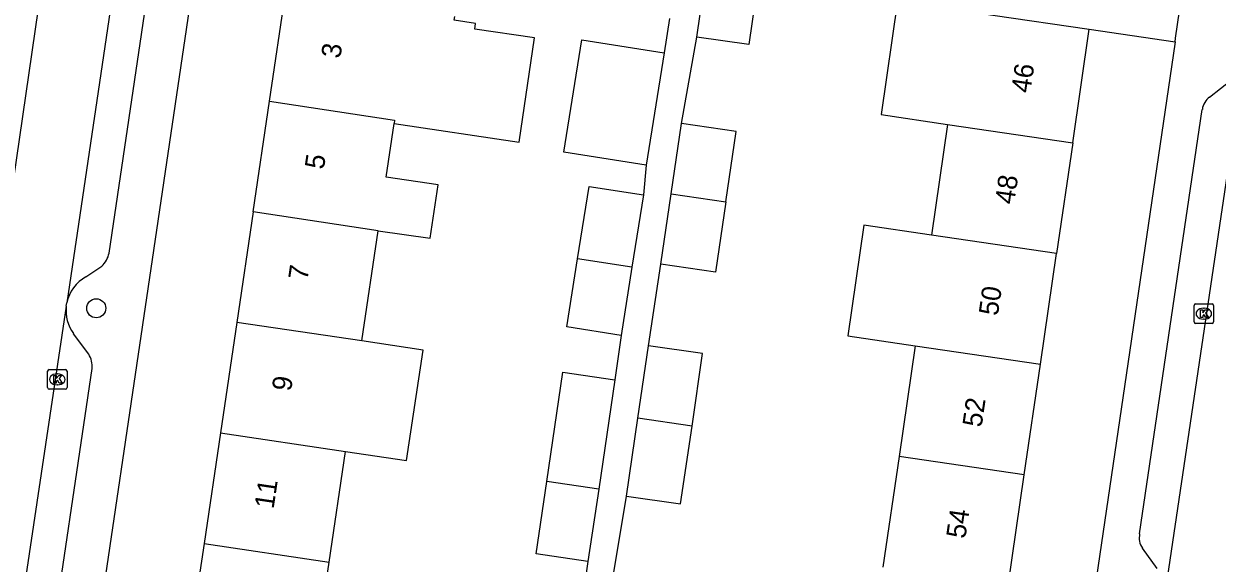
# Model space of a CAD drawing. Extents: x 163686 to 164493, y 382719 to 383870.
# Drawn here: x 163796.1 to 163857.4, y 383079.3 to 383107 of the extents above; entities that cross this region are included whole.
import ezdxf

# ---------------------------------------------------------------- set-up
doc = ezdxf.new("R2010")
doc.units = 0
for name, color, linetype in [('IMGEO_Boom', 7, 'Continuous'), ('IMGEO_Kolk', 7, 'Continuous'), ('IMGEO_Pand', 7, 'Continuous'), ('IMGEO_Pand_nummerreeks', 7, 'Continuous'), ('IMGEO_Rijbaan_lokaal_open', 7, 'Continuous'), ('IMGEO_Voetpad_open', 7, 'Continuous')]:
    doc.layers.add(name, color=color, linetype=linetype)

msp = doc.modelspace()

# ---------------------------------------------------------------- linework, layer by layer
at = {"layer": 'IMGEO_Boom'}
msp.add_circle((163799.849, 383092.402), 0.489, dxfattribs=at)
at = {"layer": 'IMGEO_Kolk'}
for p, q in [((163856.263, 383091.699), (163856.263, 383092.551)), ((163856.338, 383092.625), (163857.19, 383092.625)), ((163856.751, 383092.405), (163856.776, 383092.405)), ((163857.264, 383092.551), (163857.264, 383091.699)), ((163857.19, 383091.625), (163856.338, 383091.625)), ((163856.774, 383091.845), (163856.749, 383091.845)), ((163797.347, 383088.321), (163797.347, 383089.173)), ((163797.422, 383089.247), (163798.274, 383089.247)), ((163797.835, 383089.027), (163797.86, 383089.027)), ((163798.348, 383089.173), (163798.348, 383088.321)), ((163797.858, 383088.467), (163797.833, 383088.467)), ((163798.274, 383088.247), (163797.422, 383088.247))]:
    msp.add_line(p, q, dxfattribs=at)
for points in [[(163856.263, 383091.699), (163856.263, 383092.551)], [(163856.338, 383092.625), (163857.19, 383092.625)], [(163856.584, 383092.325), (163856.707, 383092.325), (163856.707, 383092.174), (163856.837, 383092.325), (163857.001, 383092.325), (163856.855, 383092.174), (163857.008, 383091.925), (163856.856, 383091.925), (163856.771, 383092.089), (163856.707, 383092.022), (163856.707, 383091.925), (163856.584, 383091.925), (163856.584, 383092.325)], [(163857.264, 383092.551), (163857.264, 383091.699)], [(163857.19, 383091.625), (163856.338, 383091.625)], [(163797.347, 383088.321), (163797.347, 383089.173)], [(163797.422, 383089.247), (163798.274, 383089.247)], [(163798.348, 383089.173), (163798.348, 383088.321)], [(163797.668, 383088.947), (163797.791, 383088.947), (163797.791, 383088.796), (163797.921, 383088.947), (163798.085, 383088.947), (163797.939, 383088.796), (163798.092, 383088.547), (163797.94, 383088.547), (163797.855, 383088.711), (163797.791, 383088.644), (163797.791, 383088.547), (163797.668, 383088.547), (163797.668, 383088.947)], [(163798.274, 383088.247), (163797.422, 383088.247)]]:
    msp.add_lwpolyline(points, dxfattribs=at)
for centre, start, end in [((163856.34, 383092.549), 91.55205, 178.44795), ((163856.34, 383092.549), 91.55205, 178.44795), ((163857.188, 383092.549), 1.55205, 88.44795), ((163857.188, 383092.549), 1.55205, 88.44795), ((163856.34, 383091.701), 181.55205, 268.44795), ((163856.34, 383091.701), 181.55205, 268.44795), ((163857.188, 383091.701), 271.55205, 358.44795), ((163857.188, 383091.701), 271.55205, 358.44795), ((163797.424, 383089.171), 91.55205, 178.44795), ((163797.424, 383089.171), 91.55205, 178.44795), ((163798.272, 383089.171), 1.55205, 88.44795), ((163798.272, 383089.171), 1.55205, 88.44795), ((163797.424, 383088.323), 181.55205, 268.44795), ((163797.424, 383088.323), 181.55205, 268.44795), ((163798.272, 383088.323), 271.55205, 358.44795), ((163798.272, 383088.323), 271.55205, 358.44795)]:
    msp.add_arc(centre, 0.0765, start, end, dxfattribs=at)
for centre, major_axis, ratio, start_param, end_param in [((163856.75, 383092.125), (-0.387, 0.002), 0.722429, 4.712389, 7.853982), ((163856.775, 383092.125), (-0.39, 0.002), 0.717154, 1.570796, 4.712389), ((163797.834, 383088.747), (-0.387, 0.002), 0.722429, 4.712389, 7.853982), ((163797.859, 383088.747), (-0.39, 0.002), 0.717154, 1.570796, 4.712389)]:
    msp.add_ellipse(centre, major_axis=major_axis, ratio=ratio, start_param=start_param, end_param=end_param, dxfattribs=at)
at = {"layer": 'IMGEO_Pand'}
for points in [[(163830.71, 383106.346), (163831.213, 383109.792), (163833.884, 383109.402)], [(163833.884, 383109.402), (163833.381, 383105.956), (163830.71, 383106.346)], [(163808.748, 383103.042), (163809.589, 383108.724)], [(163841.028, 383108.189), (163840.176, 383102.357), (163843.591, 383101.856)], [(163841.028, 383108.189), (163844.442, 383107.69), (163845.928, 383107.473), (163850.875, 383106.752)], [(163815.154, 383101.897), (163821.579, 383100.946), (163822.371, 383106.3), (163819.298, 383106.755), (163819.341, 383107.047), (163818.246, 383107.209), (163818.276, 383107.409)], [(163828.114, 383099.754), (163823.878, 383100.425), (163824.794, 383106.205), (163829.03, 383105.535)], [(163850.024, 383100.913), (163850.875, 383106.752)], [(163829.03, 383105.535), (163828.114, 383099.754)], [(163807.908, 383097.36), (163808.748, 383103.042)], [(163808.748, 383103.042), (163815.179, 383102.069), (163815.154, 383101.897)], [(163814.339, 383096.392), (163817.011, 383096.008), (163817.416, 383098.741), (163814.746, 383099.138), (163815.154, 383101.897)], [(163829.396, 383098.286), (163829.927, 383101.905)], [(163832.207, 383097.874), (163832.737, 383101.493), (163829.927, 383101.905)], [(163843.591, 383101.856), (163842.762, 383096.167)], [(163843.591, 383101.856), (163850.024, 383100.913)], [(163850.024, 383100.913), (163849.194, 383095.225)], [(163824.573, 383094.943), (163825.183, 383098.666), (163827.964, 383098.226)], [(163827.964, 383098.226), (163827.377, 383094.518)], [(163828.865, 383094.666), (163829.396, 383098.286)], [(163829.396, 383098.286), (163832.207, 383097.874)], [(163832.207, 383097.874), (163831.676, 383094.255), (163828.865, 383094.666)], [(163807.908, 383097.36), (163807.067, 383091.678)], [(163814.339, 383096.392), (163807.908, 383097.36)], [(163813.5, 383090.723), (163814.339, 383096.392)], [(163842.762, 383096.167), (163839.299, 383096.675), (163838.47, 383090.986), (163841.933, 383090.478)], [(163849.194, 383095.225), (163842.762, 383096.167)], [(163848.365, 383089.535), (163849.194, 383095.225)], [(163826.82, 383091.001), (163824.038, 383091.442), (163824.573, 383094.943)], [(163827.377, 383094.518), (163824.573, 383094.943)], [(163827.377, 383094.518), (163826.82, 383091.001)], [(163807.067, 383091.678), (163806.226, 383085.996)], [(163813.5, 383090.723), (163807.067, 383091.678)], [(163812.66, 383085.04), (163815.799, 383084.574), (163816.643, 383090.256), (163813.5, 383090.723)], [(163827.684, 383086.754), (163828.23, 383090.48)], [(163830.474, 383086.346), (163831.006, 383090.073), (163828.23, 383090.48)], [(163841.933, 383090.478), (163841.103, 383084.789)], [(163841.933, 383090.478), (163848.365, 383089.535)], [(163823, 383083.504), (163823.831, 383089.111), (163826.497, 383088.716)], [(163847.535, 383083.847), (163848.365, 383089.535)], [(163826.497, 383088.716), (163825.666, 383083.108)], [(163827.097, 383082.751), (163827.684, 383086.754)], [(163830.474, 383086.346), (163827.684, 383086.754)], [(163806.226, 383085.996), (163805.386, 383080.314)], [(163806.226, 383085.996), (163812.66, 383085.04)], [(163827.097, 383082.751), (163829.873, 383082.345), (163830.474, 383086.346)], [(163811.819, 383079.358), (163812.66, 383085.04)], [(163841.103, 383084.789), (163840.274, 383079.101)], [(163847.535, 383083.847), (163841.103, 383084.789)], [(163825.114, 383079.389), (163822.448, 383079.784), (163823, 383083.504)], [(163825.666, 383083.108), (163823, 383083.504)], [(163846.706, 383078.158), (163847.535, 383083.847)], [(163825.666, 383083.108), (163825.114, 383079.389)], [(163805.386, 383080.314), (163804.545, 383074.631)], [(163805.386, 383080.314), (163811.819, 383079.358)], [(163810.978, 383073.676), (163811.819, 383079.358)]]:
    msp.add_lwpolyline(points, dxfattribs=at)
at = {"layer": 'IMGEO_Rijbaan_lokaal_open'}
for points in [[(163802.171, 383118.586), (163798.337, 383092.676)], [(163794.767, 383093.408), (163797.848, 383114.451)], [(163854.78, 383077.716), (163858.894, 383105.434)], [(163798.311, 383092.512), (163798.337, 383092.676)], [(163798.311, 383092.512), (163795.125, 383071.177)]]:
    msp.add_lwpolyline(points, dxfattribs=at)
at = {"layer": 'IMGEO_Voetpad_open'}
for points in [[(163800.511, 383095.242), (163803.494, 383115.423)], [(163805.719, 383115.222), (163796.453, 383052.48)], [(163855.281, 383106.105), (163855.308, 383106.292), (163855.512, 383107.699)], [(163829.309, 383107.297), (163829.03, 383105.535)], [(163829.927, 383101.905), (163830.71, 383106.346)], [(163850.875, 383106.752), (163855.281, 383106.105)], [(163855.281, 383106.105), (163848.55, 383060.302)], [(163857.059, 383103.26), (163858.178, 383104.148)], [(163853.464, 383080.804), (163856.685, 383102.628)], [(163828.114, 383099.754), (163827.964, 383098.226)], [(163799.319, 383094.023), (163800.132, 383094.565)], [(163828.23, 383090.48), (163828.865, 383094.666)], [(163799.462, 383090.043), (163798.678, 383091.097)], [(163826.82, 383091.001), (163826.497, 383088.716)], [(163797.288, 383073.444), (163799.638, 383089.303)], [(163826.436, 383078.718), (163827.097, 383082.751)], [(163854.366, 383079.029), (163853.605, 383080.077)], [(163825.114, 383079.389), (163824.533, 383075.345)]]:
    msp.add_lwpolyline(points, dxfattribs=at)
for centre, radius, start, end in [((163857.605, 383102.51), 0.927, 126.05576, 172.71251), ((163799.138, 383095.566), 1.411, 314.79612, 346.72169), ((163800.308, 383092.27), 2.012, 119.43969, 168.37415), ((163800.303, 383092.274), 2.006, 173.17353, 215.90662), ((163798.38, 383089.395), 1.262, 355.83274, 30.92434), ((163854.361, 383080.601), 0.919, 167.22574, 214.72649)]:
    msp.add_arc(centre, radius, start, end, dxfattribs=at)

# ---------------------------------------------------------------- texts
at = {"layer": 'IMGEO_Pand_nummerreeks'}
for s, rotation, p in [('3', 81.58346, (163812.386, 383105.216)), ('46', 81.70378, (163847.845, 383103.435)), ('5', 81.58346, (163811.542, 383099.512)), ('48', 81.70484, (163847.01, 383097.712)), ('7', 81.58448, (163810.697, 383093.809)), ('50', 81.70484, (163846.175, 383091.986)), ('9', 81.58346, (163809.855, 383088.105)), ('52', 81.70484, (163845.339, 383086.254)), ('11', 81.58448, (163808.96, 383082.06)), ('54', 81.70484, (163844.505, 383080.53))]:
    msp.add_text(s, height=1, rotation=rotation, dxfattribs=at).set_placement(p)

doc.saveas('drawing.dxf')
